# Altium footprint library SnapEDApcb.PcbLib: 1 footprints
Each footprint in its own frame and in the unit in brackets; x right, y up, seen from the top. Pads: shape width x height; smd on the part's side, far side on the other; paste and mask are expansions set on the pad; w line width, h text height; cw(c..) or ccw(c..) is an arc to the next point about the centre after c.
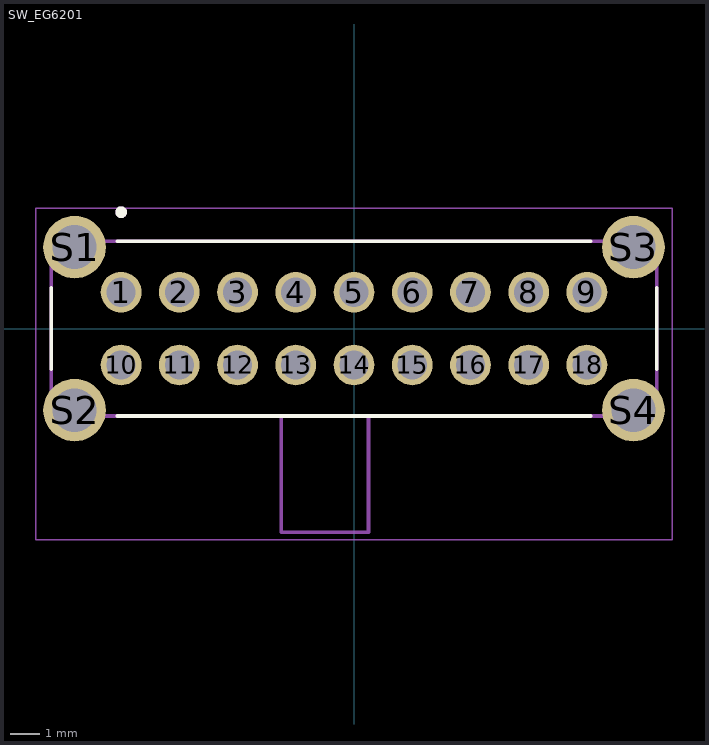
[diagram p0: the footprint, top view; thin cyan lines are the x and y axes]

## SW_EG6201 [mm]
pads (22):
  round 1.4 hole 1: 1(-8,1.25) 2(-6,1.25) 3(-4,1.25) 4(-2,1.25) 5(0,1.25) 6(2,1.25) 7(4,1.25) 8(6,1.25) 9(8,1.25) 10(-8,-1.25) 11(-6,-1.25) 12(-4,-1.25) 13(-2,-1.25) 14(0,-1.25) 15(2,-1.25) 16(4,-1.25) 17(6,-1.25) 18(8,-1.25)
  round 2.15 hole 1.5: S1(-9.6,2.8) S2(-9.6,-2.8) S3(9.6,2.8) S4(9.6,-2.8)
Top Overlay:
  circle w0.2: c-8,4 r0.1
  lines w0.127: -10.4,-1.4 -10.4,1.4 ; -8.125,-3 8.125,-3 ; -8.125,3 8.125,3 ; 10.4,-1.4 10.4,1.4
Mechanical 13:
  circle w0.2: c-8,4 r0.1
  lines w0.127: -2.5,-3 -2.5,-7 0.5,-7 0.5,-3 ; -2.5,-3 -10.4,-3 -10.4,3 10.4,3 10.4,-3 0.5,-3 ; -2.5,-3 0.5,-3
Mechanical 15:
  lines w0.05: -10.93,-7.25 -10.93,4.13 10.93,4.13 10.93,-7.25 -10.93,-7.25
3D body "EG6201--3DModel-STEP-56544.STEP": height 5, standoff -3, extent -10.414,-6.985 10.386,3.015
